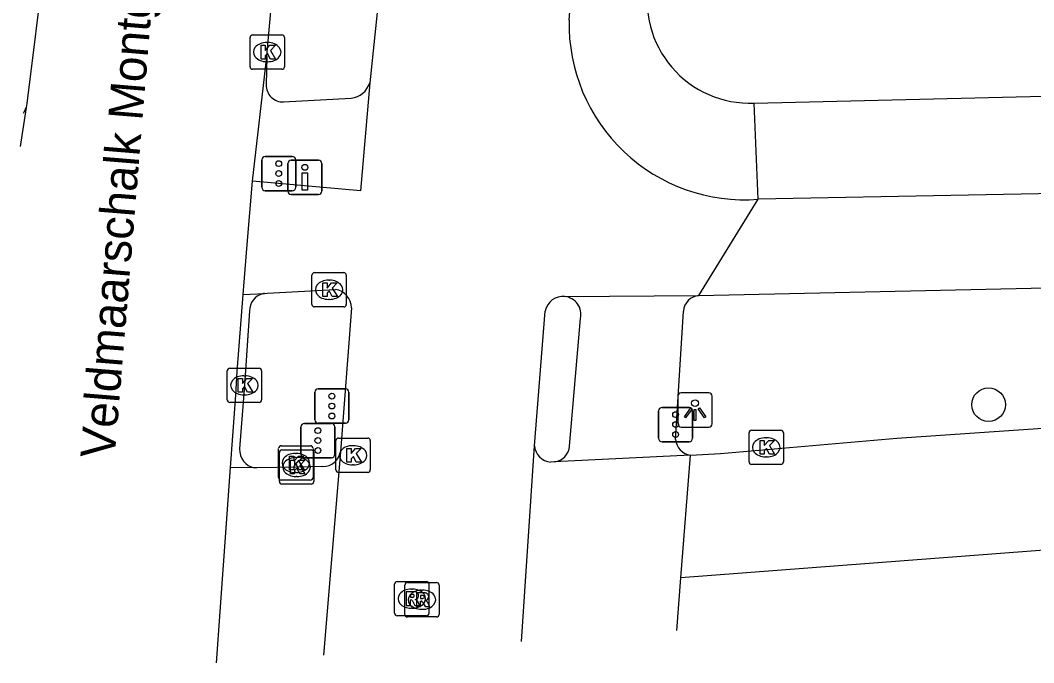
# Model space of a CAD drawing. Extents: x 161243 to 161752, y 384138 to 384885.
# Drawn here: x 161242.75 to 161272.28, y 384138.41 to 384157.14 of the extents above; entities that cross this region are included whole.
import ezdxf

# ---------------------------------------------------------------- set-up
doc = ezdxf.new("R2010")
doc.units = 0
for name, color, linetype in [('IMGEO_Boom', 7, 'Continuous'), ('IMGEO_Drukknoppaal', 7, 'Continuous'), ('IMGEO_Fietspad_gesloten', 7, 'Continuous'), ('IMGEO_Kolk', 7, 'Continuous'), ('IMGEO_Lichtpunt', 7, 'Continuous'), ('IMGEO_Openbare_ruimte_label', 7, 'Continuous'), ('IMGEO_OVBaan_gesloten', 7, 'Continuous'), ('IMGEO_Rijbaan_lokaal_gesloten', 7, 'Continuous'), ('IMGEO_Rioolput', 7, 'Continuous'), ('IMGEO_Verkeersregelinstallatiepaal', 7, 'Continuous'), ('IMGEO_Voetpad_open', 7, 'Continuous')]:
    doc.layers.add(name, color=color, linetype=linetype)

msp = doc.modelspace()

# ---------------------------------------------------------------- linework, layer by layer
at = {"layer": 'IMGEO_Boom'}
msp.add_circle((161270.962, 384145.932), 0.489, dxfattribs=at)
at = {"layer": 'IMGEO_Drukknoppaal'}
for p, q in [((161250.549, 384152.159), (161250.549, 384152.959)), ((161250.549, 384152.959), (161250.549, 384152.159)), ((161250.649, 384153.059), (161251.439, 384153.059)), ((161251.439, 384153.059), (161250.649, 384153.059)), ((161251.539, 384152.959), (161251.539, 384152.159)), ((161251.539, 384152.159), (161251.539, 384152.959)), ((161251.439, 384152.059), (161250.649, 384152.059)), ((161250.649, 384152.059), (161251.439, 384152.059))]:
    msp.add_line(p, q, dxfattribs=at)
msp.add_lwpolyline([(161251.119, 384152.684), (161251.119, 384152.184), (161250.969, 384152.184), (161250.969, 384152.684), (161251.119, 384152.684)], dxfattribs=at)
msp.add_circle((161251.044, 384152.849), 0.085, dxfattribs=at)
for centre, start, end in [((161250.649, 384152.959), 90, 180), ((161250.649, 384152.959), 90, 180), ((161251.439, 384152.959), 0, 90), ((161251.439, 384152.959), 360, 90), ((161250.649, 384152.159), 180, 270), ((161250.649, 384152.159), 180, 270), ((161251.439, 384152.159), 270, 0), ((161251.439, 384152.159), 270, 0)]:
    msp.add_arc(centre, 0.1, start, end, dxfattribs=at)
at = {"layer": 'IMGEO_Fietspad_gesloten'}
for points in [[(161258.742, 384157.135), (161260.876, 384184.71), (161262.854, 384210.484), (161266.448, 384261.586), (161267.146, 384270.325), (161268.291, 384284.663), (161268.569, 384287.683), (161268.583, 384287.814)], [(161263.994, 384275.849), (161263.983, 384275.709), (161263.143, 384264.813), (161262.927, 384262.016), (161262.305, 384253.304), (161261.604, 384243.474), (161259.279, 384210.879), (161257.318, 384184.907), (161257.099, 384182.165), (161256.945, 384180.975), (161255.727, 384175.693), (161255.111, 384172.583), (161254.402, 384168.209), (161253.797, 384163.617), (161252.937, 384155.312)], [(161252.937, 384155.312), (161252.667, 384152.165), (161249.515, 384152.442)], [(161335.217, 384153.424), (161294.886, 384152.501), (161264.254, 384151.917)], [(161262.525, 384149.114), (161264.254, 384151.917)], [(161262.525, 384149.114), (161334.701, 384150.711)], [(161249.868, 384149.175), (161249.943, 384149.179), (161251.751, 384149.281), (161251.938, 384149.291)], [(161258.616, 384149.084), (161262.525, 384149.114)], [(161252.404, 384148.752), (161252.083, 384144.555)], [(161257.733, 384144.737), (161258.049, 384148.661)]]:
    msp.add_lwpolyline(points, dxfattribs=at)
for centre, radius, start, end in [((161263.865, 384157.027), 5.125, 178.7899, 274.3491), ((161251.856, 384148.749), 0.548, 0.2994, 81.3916), ((161258.563, 384148.564), 0.523, 84.1247, 169.3235)]:
    msp.add_arc(centre, radius, start, end, dxfattribs=at)
at = {"layer": 'IMGEO_Kolk'}
for p, q in [((161249.523, 384156.706), (161250.375, 384156.706)), ((161249.448, 384155.78), (161249.448, 384156.632)), ((161249.936, 384156.486), (161249.961, 384156.486)), ((161250.449, 384156.632), (161250.449, 384155.78)), ((161249.959, 384155.926), (161249.934, 384155.926)), ((161250.375, 384155.706), (161249.523, 384155.706)), ((161251.25, 384148.855), (161251.25, 384149.707)), ((161251.325, 384149.781), (161252.177, 384149.781)), ((161252.251, 384149.707), (161252.251, 384148.855)), ((161251.738, 384149.561), (161251.763, 384149.561)), ((161251.761, 384149.001), (161251.736, 384149.001)), ((161252.177, 384148.781), (161251.325, 384148.781)), ((161248.782, 384146.071), (161248.782, 384146.923)), ((161248.857, 384146.997), (161249.709, 384146.997)), ((161249.783, 384146.923), (161249.783, 384146.071)), ((161249.27, 384146.777), (161249.295, 384146.777)), ((161249.293, 384146.217), (161249.268, 384146.217)), ((161249.709, 384145.997), (161248.857, 384145.997)), ((161264.059, 384145.189), (161264.911, 384145.189)), ((161251.948, 384144.032), (161251.948, 384144.884)), ((161252.023, 384144.958), (161252.875, 384144.958)), ((161252.949, 384144.884), (161252.949, 384144.032)), ((161263.984, 384144.263), (161263.984, 384145.115)), ((161264.472, 384144.969), (161264.497, 384144.969)), ((161264.985, 384145.115), (161264.985, 384144.263)), ((161250.28, 384143.808), (161250.28, 384144.66)), ((161250.355, 384144.734), (161251.207, 384144.734)), ((161250.377, 384144.615), (161251.229, 384144.615)), ((161251.281, 384144.66), (161251.281, 384143.808)), ((161252.436, 384144.738), (161252.461, 384144.738)), ((161250.302, 384143.689), (161250.302, 384144.541)), ((161250.768, 384144.514), (161250.793, 384144.514)), ((161250.79, 384144.395), (161250.815, 384144.395)), ((161251.303, 384144.541), (161251.303, 384143.689)), ((161264.495, 384144.409), (161264.47, 384144.409)), ((161252.459, 384144.178), (161252.434, 384144.178)), ((161264.911, 384144.189), (161264.059, 384144.189)), ((161251.207, 384143.734), (161250.355, 384143.734)), ((161250.791, 384143.954), (161250.766, 384143.954)), ((161250.813, 384143.835), (161250.788, 384143.835)), ((161252.875, 384143.958), (161252.023, 384143.958)), ((161251.229, 384143.615), (161250.377, 384143.615))]:
    msp.add_line(p, q, dxfattribs=at)
for points in [[(161249.523, 384156.706), (161250.375, 384156.706)], [(161249.448, 384155.78), (161249.448, 384156.632)], [(161249.769, 384156.406), (161249.892, 384156.406), (161249.892, 384156.255), (161250.022, 384156.406), (161250.186, 384156.406), (161250.04, 384156.255), (161250.193, 384156.006), (161250.041, 384156.006), (161249.956, 384156.17), (161249.892, 384156.103), (161249.892, 384156.006), (161249.769, 384156.006), (161249.769, 384156.406)], [(161250.449, 384156.632), (161250.449, 384155.78)], [(161250.375, 384155.706), (161249.523, 384155.706)], [(161251.25, 384148.855), (161251.25, 384149.707)], [(161251.325, 384149.781), (161252.177, 384149.781)], [(161252.251, 384149.707), (161252.251, 384148.855)], [(161251.571, 384149.481), (161251.694, 384149.481), (161251.694, 384149.33), (161251.824, 384149.481), (161251.988, 384149.481), (161251.842, 384149.33), (161251.995, 384149.081), (161251.843, 384149.081), (161251.758, 384149.245), (161251.694, 384149.178), (161251.694, 384149.081), (161251.571, 384149.081), (161251.571, 384149.481)], [(161252.177, 384148.781), (161251.325, 384148.781)], [(161248.782, 384146.071), (161248.782, 384146.923)], [(161248.857, 384146.997), (161249.709, 384146.997)], [(161249.783, 384146.923), (161249.783, 384146.071)], [(161249.103, 384146.697), (161249.226, 384146.697), (161249.226, 384146.546), (161249.356, 384146.697), (161249.52, 384146.697), (161249.374, 384146.546), (161249.527, 384146.297), (161249.375, 384146.297), (161249.29, 384146.461), (161249.226, 384146.394), (161249.226, 384146.297), (161249.103, 384146.297), (161249.103, 384146.697)], [(161249.709, 384145.997), (161248.857, 384145.997)], [(161264.059, 384145.189), (161264.911, 384145.189)], [(161251.948, 384144.032), (161251.948, 384144.884)], [(161252.023, 384144.958), (161252.875, 384144.958)], [(161252.949, 384144.884), (161252.949, 384144.032)], [(161263.984, 384144.263), (161263.984, 384145.115)], [(161264.305, 384144.889), (161264.428, 384144.889), (161264.428, 384144.738), (161264.558, 384144.889), (161264.722, 384144.889), (161264.576, 384144.738), (161264.729, 384144.489), (161264.577, 384144.489), (161264.492, 384144.653), (161264.428, 384144.586), (161264.428, 384144.489), (161264.305, 384144.489), (161264.305, 384144.889)], [(161264.985, 384145.115), (161264.985, 384144.263)], [(161250.28, 384143.808), (161250.28, 384144.66)], [(161250.355, 384144.734), (161251.207, 384144.734)], [(161250.377, 384144.615), (161251.229, 384144.615)], [(161251.281, 384144.66), (161251.281, 384143.808)], [(161252.269, 384144.658), (161252.392, 384144.658), (161252.392, 384144.507), (161252.522, 384144.658), (161252.686, 384144.658), (161252.54, 384144.507), (161252.693, 384144.258), (161252.541, 384144.258), (161252.456, 384144.422), (161252.392, 384144.355), (161252.392, 384144.258), (161252.269, 384144.258), (161252.269, 384144.658)], [(161250.302, 384143.689), (161250.302, 384144.541)], [(161250.601, 384144.434), (161250.724, 384144.434), (161250.724, 384144.283), (161250.854, 384144.434), (161251.018, 384144.434), (161250.872, 384144.283), (161251.025, 384144.034), (161250.873, 384144.034), (161250.788, 384144.198), (161250.724, 384144.131), (161250.724, 384144.034), (161250.601, 384144.034), (161250.601, 384144.434)], [(161250.623, 384144.315), (161250.746, 384144.315), (161250.746, 384144.164), (161250.876, 384144.315), (161251.04, 384144.315), (161250.894, 384144.164), (161251.047, 384143.915), (161250.895, 384143.915), (161250.81, 384144.079), (161250.746, 384144.012), (161250.746, 384143.915), (161250.623, 384143.915), (161250.623, 384144.315)], [(161251.303, 384144.541), (161251.303, 384143.689)], [(161264.911, 384144.189), (161264.059, 384144.189)], [(161251.207, 384143.734), (161250.355, 384143.734)], [(161252.875, 384143.958), (161252.023, 384143.958)], [(161251.229, 384143.615), (161250.377, 384143.615)]]:
    msp.add_lwpolyline(points, dxfattribs=at)
for centre, start, end in [((161249.525, 384156.63), 91.552, 178.448), ((161249.525, 384156.63), 91.552, 178.448), ((161250.373, 384156.63), 1.552, 88.448), ((161250.373, 384156.63), 1.552, 88.448), ((161249.525, 384155.782), 181.552, 268.448), ((161249.525, 384155.782), 181.552, 268.448), ((161250.373, 384155.782), 271.552, 358.448), ((161250.373, 384155.782), 271.552, 358.448), ((161251.327, 384149.705), 91.552, 178.448), ((161251.327, 384149.705), 91.552, 178.448), ((161252.175, 384149.705), 1.552, 88.448), ((161252.175, 384149.705), 1.552, 88.448), ((161251.327, 384148.857), 181.552, 268.448), ((161251.327, 384148.857), 181.552, 268.448), ((161252.175, 384148.857), 271.552, 358.448), ((161252.175, 384148.857), 271.552, 358.448), ((161248.859, 384146.921), 91.552, 178.448), ((161248.859, 384146.921), 91.552, 178.448), ((161249.707, 384146.921), 1.552, 88.448), ((161249.707, 384146.921), 1.552, 88.448), ((161248.859, 384146.073), 181.552, 268.448), ((161248.859, 384146.073), 181.552, 268.448), ((161249.707, 384146.073), 271.552, 358.448), ((161249.707, 384146.073), 271.552, 358.448), ((161264.061, 384145.113), 91.552, 178.448), ((161264.061, 384145.113), 91.552, 178.448), ((161264.909, 384145.113), 1.552, 88.448), ((161264.909, 384145.113), 1.552, 88.448), ((161252.025, 384144.882), 91.552, 178.448), ((161252.025, 384144.882), 91.552, 178.448), ((161252.873, 384144.882), 1.552, 88.448), ((161252.873, 384144.882), 1.552, 88.448), ((161250.357, 384144.658), 91.552, 178.448), ((161250.357, 384144.658), 91.552, 178.448), ((161250.379, 384144.539), 91.552, 178.448), ((161250.379, 384144.539), 91.552, 178.448), ((161251.205, 384144.658), 1.552, 88.448), ((161251.205, 384144.658), 1.552, 88.448), ((161251.227, 384144.539), 1.552, 88.448), ((161251.227, 384144.539), 1.552, 88.448), ((161252.025, 384144.034), 181.552, 268.448), ((161252.025, 384144.034), 181.552, 268.448), ((161252.873, 384144.034), 271.552, 358.448), ((161252.873, 384144.034), 271.552, 358.448), ((161264.061, 384144.265), 181.552, 268.448), ((161264.061, 384144.265), 181.552, 268.448), ((161264.909, 384144.265), 271.552, 358.448), ((161264.909, 384144.265), 271.552, 358.448), ((161250.357, 384143.81), 181.552, 268.448), ((161250.357, 384143.81), 181.552, 268.448), ((161250.379, 384143.691), 181.552, 268.448), ((161250.379, 384143.691), 181.552, 268.448), ((161251.205, 384143.81), 271.552, 358.448), ((161251.205, 384143.81), 271.552, 358.448), ((161251.227, 384143.691), 271.552, 358.448), ((161251.227, 384143.691), 271.552, 358.448)]:
    msp.add_arc(centre, 0.0765, start, end, dxfattribs=at)
for centre, major_axis, ratio, start_param, end_param in [((161249.935, 384156.206), (-0.387, 0.002), 0.722429, 4.712389, 7.853982), ((161249.96, 384156.206), (-0.39, 0.002), 0.717154, 1.570796, 4.712389), ((161251.737, 384149.281), (-0.387, 0.002), 0.722429, 4.712389, 7.853982), ((161251.762, 384149.281), (-0.39, 0.002), 0.717154, 1.570796, 4.712389), ((161249.269, 384146.497), (-0.387, 0.002), 0.722429, 4.712389, 7.853982), ((161249.294, 384146.497), (-0.39, 0.002), 0.717154, 1.570796, 4.712389), ((161264.471, 384144.689), (-0.387, 0.002), 0.722429, 4.712389, 7.853982), ((161264.496, 384144.689), (-0.39, 0.002), 0.717154, 1.570796, 4.712389), ((161252.435, 384144.458), (-0.387, 0.002), 0.722429, 4.712389, 7.853982), ((161252.46, 384144.458), (-0.39, 0.002), 0.717154, 1.570796, 4.712389), ((161250.767, 384144.234), (-0.387, 0.002), 0.722429, 4.712389, 7.853982), ((161250.789, 384144.115), (-0.387, 0.002), 0.722429, 4.712389, 7.853982), ((161250.792, 384144.234), (-0.39, 0.002), 0.717154, 1.570796, 4.712389), ((161250.814, 384144.115), (-0.39, 0.002), 0.717154, 1.570796, 4.712389)]:
    msp.add_ellipse(centre, major_axis=major_axis, ratio=ratio, start_param=start_param, end_param=end_param, dxfattribs=at)
at = {"layer": 'IMGEO_Lichtpunt'}
for p, q in [((161261.912, 384146.178), (161261.912, 384145.371)), ((161261.912, 384146.178), (161261.912, 384145.371)), ((161262.814, 384146.273), (161262.006, 384146.273)), ((161262.814, 384146.273), (161262.006, 384146.273)), ((161262.908, 384145.371), (161262.908, 384146.178)), ((161262.908, 384145.371), (161262.908, 384146.178)), ((161262.006, 384145.277), (161262.814, 384145.277)), ((161262.006, 384145.277), (161262.814, 384145.277))]:
    msp.add_line(p, q, dxfattribs=at)
for points in [[(161262.286, 384145.842), (161262.325, 384145.814), (161262.137, 384145.552), (161262.099, 384145.579), (161262.286, 384145.842)], [(161262.388, 384145.794), (161262.435, 384145.794), (161262.435, 384145.472), (161262.388, 384145.472), (161262.388, 384145.794)], [(161262.498, 384145.814), (161262.536, 384145.841), (161262.723, 384145.579), (161262.684, 384145.551), (161262.498, 384145.814)]]:
    msp.add_lwpolyline(points, dxfattribs=at)
msp.add_circle((161262.411, 384145.976), 0.0994, dxfattribs=at)
for centre, start, end in [((161262.006, 384146.178), 90, 180), ((161262.006, 384146.178), 90, 180), ((161262.814, 384146.178), 0, 90), ((161262.814, 384146.178), 0, 90), ((161262.006, 384145.371), 180, 270), ((161262.006, 384145.371), 180, 270), ((161262.814, 384145.371), 270, 0), ((161262.814, 384145.371), 270, 360)]:
    msp.add_arc(centre, 0.0946, start, end, dxfattribs=at)
at = {"layer": 'IMGEO_OVBaan_gesloten'}
for points in [[(161249.934, 384156.079), (161249.949, 384156.206), (161250.106, 384158.053), (161251.316, 384173.143), (161251.591, 384176.567), (161253.117, 384195.97), (161254.778, 384217.347), (161256.24, 384236.299), (161258.002, 384258.664), (161259.312, 384275.054), (161259.367, 384276.07), (161259.381, 384276.22)], [(161244.663, 384173.474), (161243.814, 384162.675), (161243.598, 384159.911), (161243.455, 384158.862), (161242.942, 384154.711), (161242.923, 384154.593)], [(161249.515, 384152.442), (161249.934, 384156.079)], [(161242.923, 384154.593), (161242.753, 384153.458)], [(161249.247, 384149.144), (161249.36, 384150.604), (161249.515, 384152.442)], [(161248.881, 384144.099), (161249.035, 384146.209), (161249.074, 384146.898), (161249.247, 384149.144)], [(161248.466, 384138.412), (161248.881, 384144.099)]]:
    msp.add_lwpolyline(points, dxfattribs=at)
at = {"layer": 'IMGEO_Rijbaan_lokaal_gesloten'}
for points in [[(161403.252, 384150.18), (161392.155, 384149.886), (161376.721, 384149.233), (161369.626, 384148.76), (161361.232, 384148.2), (161341.125, 384146.731), (161314.989, 384144.831), (161288.79, 384142.926), (161262, 384140.882)], [(161262.281, 384144.461), (161263.157, 384144.513), (161268.286, 384144.952), (161279.348, 384145.71), (161300.005, 384147.288), (161301.599, 384147.407), (161303.55, 384147.498), (161305.252, 384147.652), (161308.927, 384147.935), (161315.164, 384148.38), (161319.129, 384148.659), (161324.063, 384148.934), (161328.631, 384149.374), (161334.833, 384149.765)], [(161249.247, 384149.144), (161249.868, 384149.175)], [(161249.868, 384149.175), (161249.841, 384149.17), (161249.815, 384149.164)], [(161249.434, 384148.663), (161249.283, 384146.497), (161249.142, 384144.643)], [(161257.359, 384139.032), (161257.733, 384144.737)], [(161252.083, 384144.555), (161251.589, 384138.63)], [(161262.281, 384144.461), (161258.321, 384144.263)], [(161262, 384140.882), (161262.281, 384144.461)], [(161249.577, 384144.095), (161248.881, 384144.099)], [(161251.568, 384144.133), (161250.803, 384144.115), (161249.641, 384144.087), (161249.577, 384144.095)], [(161258.321, 384144.263), (161258.204, 384144.259)], [(161261.88, 384139.347), (161262, 384140.882)]]:
    msp.add_lwpolyline(points, dxfattribs=at)
for centre, radius, start, end in [((161249.934, 384148.678), 0.5, 103.7367, 181.7589), ((161249.67, 384144.616), 0.529, 177.0371, 259.8477), ((161258.245, 384144.771), 0.513, 183.7711, 265.3837), ((161251.571, 384144.654), 0.521, 269.6327, 349.0309)]:
    msp.add_arc(centre, radius, start, end, dxfattribs=at)
at = {"layer": 'IMGEO_Rioolput'}
for p, q in [((161253.734, 384140.78), (161254.586, 384140.78)), ((161254.03, 384140.748), (161254.882, 384140.748)), ((161253.659, 384139.854), (161253.659, 384140.706)), ((161253.955, 384139.822), (161253.955, 384140.674)), ((161254.147, 384140.56), (161254.172, 384140.56)), ((161254.443, 384140.528), (161254.468, 384140.528)), ((161254.66, 384140.706), (161254.66, 384139.854)), ((161254.956, 384140.674), (161254.956, 384139.822)), ((161254.17, 384140), (161254.145, 384140)), ((161254.466, 384139.968), (161254.441, 384139.968)), ((161254.586, 384139.78), (161253.734, 384139.78)), ((161254.882, 384139.748), (161254.03, 384139.748))]:
    msp.add_line(p, q, dxfattribs=at)
for points in [[(161253.734, 384140.78), (161254.586, 384140.78)], [(161254.03, 384140.748), (161254.882, 384140.748)], [(161253.659, 384139.854), (161253.659, 384140.706)], [(161253.955, 384139.822), (161253.955, 384140.674)], [(161254.248, 384140.478), (161253.996, 384140.48), (161253.996, 384140.08)], [(161254.544, 384140.446), (161254.292, 384140.448), (161254.292, 384140.048)], [(161254.66, 384140.706), (161254.66, 384139.854)], [(161254.956, 384140.674), (161254.956, 384139.822)], [(161253.996, 384140.08), (161254.12, 384140.08), (161254.12, 384140.242), (161254.131, 384140.242)], [(161254.174, 384140.399), (161254.12, 384140.399), (161254.12, 384140.318)], [(161254.12, 384140.318), (161254.172, 384140.318)], [(161254.178, 384140.213), (161254.249, 384140.08), (161254.389, 384140.08), (161254.324, 384140.206)], [(161254.292, 384140.048), (161254.416, 384140.048), (161254.416, 384140.21), (161254.427, 384140.21)], [(161254.47, 384140.367), (161254.416, 384140.367), (161254.416, 384140.286)], [(161254.416, 384140.286), (161254.468, 384140.286)], [(161254.474, 384140.181), (161254.545, 384140.048), (161254.685, 384140.048), (161254.62, 384140.174)], [(161254.586, 384139.78), (161253.734, 384139.78)], [(161254.882, 384139.748), (161254.03, 384139.748)]]:
    msp.add_lwpolyline(points, dxfattribs=at)
for centre, radius, start, end in [((161253.736, 384140.704), 0.0765, 91.552, 178.448), ((161253.736, 384140.704), 0.0765, 91.552, 178.448), ((161254.032, 384140.672), 0.0765, 91.552, 178.448), ((161254.032, 384140.672), 0.0765, 91.552, 178.448), ((161254.584, 384140.704), 0.0765, 1.552, 88.448), ((161254.584, 384140.704), 0.0765, 1.552, 88.448), ((161254.88, 384140.672), 0.0765, 1.552, 88.448), ((161254.88, 384140.672), 0.0765, 1.552, 88.448), ((161254.247, 384140.368), 0.109, 350.3612, 89.416), ((161254.543, 384140.336), 0.109, 350.3612, 89.416), ((161254.13, 384140.189), 0.0533, 26.0293, 88.6989), ((161254.156, 384140.507), 0.19, 274.7715, 282.9687), ((161254.18, 384140.303), 0.0964, 77.0061, 93.1865), ((161254.194, 384140.36), 0.0378, 276.6634, 79.6772), ((161254.245, 384140.368), 0.112, 277.5842, 350.9817), ((161254.229, 384140.153), 0.108, 29.5134, 73.7905), ((161254.426, 384140.157), 0.0533, 26.0293, 88.6989), ((161254.452, 384140.475), 0.19, 274.7715, 282.9687), ((161254.476, 384140.271), 0.0964, 77.0061, 93.1865), ((161254.49, 384140.328), 0.0378, 276.6634, 79.6772), ((161254.541, 384140.336), 0.112, 277.5842, 350.9817), ((161254.525, 384140.121), 0.108, 29.5134, 73.7905), ((161253.736, 384139.856), 0.0765, 181.552, 268.448), ((161253.736, 384139.856), 0.0765, 181.552, 268.448), ((161254.584, 384139.856), 0.0765, 271.552, 358.448), ((161254.584, 384139.856), 0.0765, 271.552, 358.448), ((161254.032, 384139.824), 0.0765, 181.552, 268.448), ((161254.032, 384139.824), 0.0765, 181.552, 268.448), ((161254.88, 384139.824), 0.0765, 271.552, 358.448), ((161254.88, 384139.824), 0.0765, 271.552, 358.448)]:
    msp.add_arc(centre, radius, start, end, dxfattribs=at)
for centre, major_axis, ratio, start_param, end_param in [((161254.146, 384140.28), (-0.387, 0.002), 0.722429, 4.712389, 7.853982), ((161254.442, 384140.248), (-0.387, 0.002), 0.722429, 4.712389, 7.853982), ((161254.171, 384140.28), (-0.39, 0.002), 0.717154, 1.570796, 4.712389), ((161254.467, 384140.248), (-0.39, 0.002), 0.717154, 1.570796, 4.712389)]:
    msp.add_ellipse(centre, major_axis=major_axis, ratio=ratio, start_param=start_param, end_param=end_param, dxfattribs=at)
at = {"layer": 'IMGEO_Verkeersregelinstallatiepaal'}
for p, q in [((161249.888, 384153.167), (161250.678, 384153.167)), ((161250.678, 384153.167), (161249.888, 384153.167)), ((161249.788, 384152.267), (161249.788, 384153.067)), ((161249.788, 384153.067), (161249.788, 384152.267)), ((161250.778, 384153.067), (161250.778, 384152.267)), ((161250.778, 384152.267), (161250.778, 384153.067)), ((161250.678, 384152.167), (161249.888, 384152.167)), ((161249.888, 384152.167), (161250.678, 384152.167)), ((161251.436, 384146.392), (161252.226, 384146.392)), ((161252.226, 384146.392), (161251.436, 384146.392)), ((161251.336, 384145.492), (161251.336, 384146.292)), ((161251.336, 384146.292), (161251.336, 384145.492)), ((161252.326, 384146.292), (161252.326, 384145.492)), ((161252.326, 384145.492), (161252.326, 384146.292)), ((161261.349, 384144.952), (161261.349, 384145.752)), ((161261.349, 384145.752), (161261.349, 384144.952)), ((161261.449, 384145.852), (161262.239, 384145.852)), ((161262.239, 384145.852), (161261.449, 384145.852)), ((161262.339, 384145.752), (161262.339, 384144.952)), ((161262.339, 384144.952), (161262.339, 384145.752)), ((161250.929, 384144.486), (161250.929, 384145.286)), ((161250.929, 384145.286), (161250.929, 384144.486)), ((161251.029, 384145.386), (161251.819, 384145.386)), ((161251.819, 384145.386), (161251.029, 384145.386)), ((161252.226, 384145.392), (161251.436, 384145.392)), ((161251.436, 384145.392), (161252.226, 384145.392)), ((161251.919, 384145.286), (161251.919, 384144.486)), ((161251.919, 384144.486), (161251.919, 384145.286)), ((161262.239, 384144.852), (161261.449, 384144.852)), ((161261.449, 384144.852), (161262.239, 384144.852)), ((161251.819, 384144.386), (161251.029, 384144.386)), ((161251.029, 384144.386), (161251.819, 384144.386))]:
    msp.add_line(p, q, dxfattribs=at)
for centre in [(161250.283, 384152.957), (161250.283, 384152.667), (161250.283, 384152.377), (161251.831, 384146.182), (161251.831, 384145.892), (161251.831, 384145.602), (161261.844, 384145.642), (161251.424, 384145.176), (161261.844, 384145.352), (161251.424, 384144.886), (161261.844, 384145.062), (161251.424, 384144.596)]:
    msp.add_circle(centre, 0.085, dxfattribs=at)
for centre, start, end in [((161249.888, 384153.067), 90, 180), ((161249.888, 384153.067), 90, 180), ((161250.678, 384153.067), 0, 90), ((161250.678, 384153.067), 360, 90), ((161249.888, 384152.267), 180, 270), ((161249.888, 384152.267), 180, 270), ((161250.678, 384152.267), 270, 0), ((161250.678, 384152.267), 270, 0), ((161251.436, 384146.292), 90, 180), ((161251.436, 384146.292), 90, 180), ((161252.226, 384146.292), 0, 90), ((161252.226, 384146.292), 360, 90), ((161261.449, 384145.752), 90, 180), ((161261.449, 384145.752), 90, 180), ((161262.239, 384145.752), 0, 90), ((161262.239, 384145.752), 360, 90), ((161251.436, 384145.492), 180, 270), ((161251.436, 384145.492), 180, 270), ((161252.226, 384145.492), 270, 0), ((161252.226, 384145.492), 270, 0), ((161251.029, 384145.286), 90, 180), ((161251.029, 384145.286), 90, 180), ((161251.819, 384145.286), 0, 90), ((161251.819, 384145.286), 360, 90), ((161261.449, 384144.952), 180, 270), ((161261.449, 384144.952), 180, 270), ((161262.239, 384144.952), 270, 0), ((161262.239, 384144.952), 270, 0), ((161251.029, 384144.486), 180, 270), ((161251.029, 384144.486), 180, 270), ((161251.819, 384144.486), 270, 0), ((161251.819, 384144.486), 270, 0)]:
    msp.add_arc(centre, 0.1, start, end, dxfattribs=at)
at = {"layer": 'IMGEO_Voetpad_open'}
for points in [[(161249.934, 384156.079), (161249.919, 384155.257)], [(161264.132, 384154.723), (161301.504, 384155.623)], [(161250.426, 384154.756), (161252.393, 384154.863)], [(161264.254, 384151.917), (161264.132, 384154.723)], [(161258.758, 384144.721), (161259.073, 384148.448)], [(161261.844, 384144.917), (161262.07, 384148.658)]]:
    msp.add_lwpolyline(points, dxfattribs=at)
for centre, radius, start, end in [((161264.005, 384157.712), 2.992, 168.7916, 272.4322), ((161250.403, 384155.24), 0.485, 177.9861, 272.696), ((161252.304, 384155.525), 0.668, 277.6689, 341.4015), ((161242.426, 384154.731), 0.516, 324.4253, 344.4654), ((161258.564, 384148.564), 0.522, 347.1399, 84.2586), ((161262.56, 384148.624), 0.491, 94.1089, 176.0169), ((161262.346, 384144.961), 0.504, 184.9568, 262.6054), ((161258.247, 384144.771), 0.513, 278.2447, 354.4435)]:
    msp.add_arc(centre, radius, start, end, dxfattribs=at)

# ---------------------------------------------------------------- texts
at = {"layer": 'IMGEO_Openbare_ruimte_label'}
msp.add_text('Veldmaarschalk Montgomerylaan', height=1, rotation=85.2982, dxfattribs=at).set_placement((161245.499, 384144.341))

doc.saveas('drawing.dxf')
